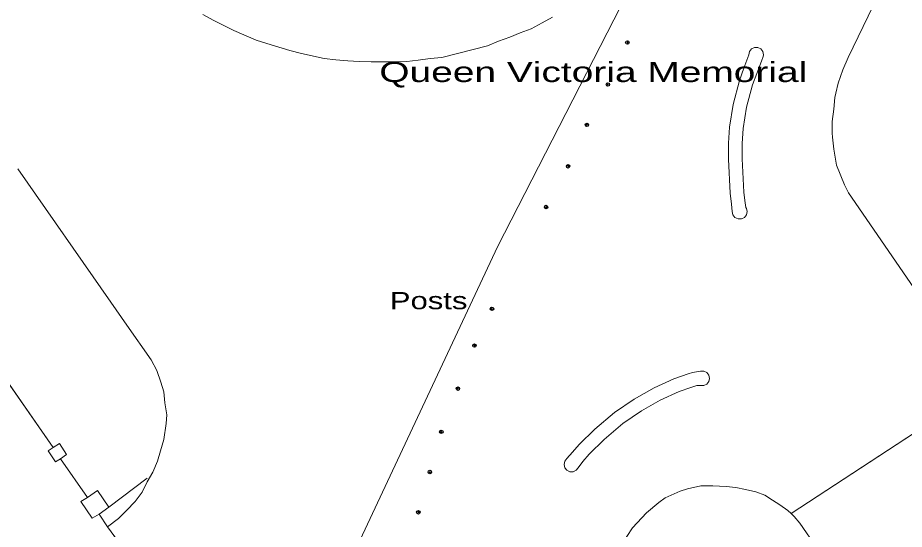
# Model space of a CAD drawing. Extents: x 528790 to 529292, y 179350 to 179856.
# Drawn here: x 529122.8 to 529200.1, y 179668.3 to 179712.9 of the extents above; entities that cross this region are included whole.
import ezdxf

# ---------------------------------------------------------------- set-up
doc = ezdxf.new("R2010")
doc.units = 0
doc.header["$LTSCALE"] = 0.6
doc.header["$PDMODE"] = 32
doc.header["$PDSIZE"] = 0.3
doc.layers.add('1', color=7, linetype='Continuous', lineweight=13)
doc.layers.add('2', color=7, linetype='Continuous', lineweight=13)
doc.layers.add('3', color=7, linetype='Continuous')
doc.layers.add('5', color=7, linetype='Continuous')

msp = doc.modelspace()

# ---------------------------------------------------------------- linework, layer by layer
at = {"layer": '1'}
for points in [[(529204.29, 179733.98), (529185.48, 179736.56), (529185.29, 179734.94), (529184.88, 179732.7), (529184.31, 179730.49), (529183.69, 179728.59), (529182.98, 179726.73), (529182.04, 179724.7), (529180.94, 179722.75), (529179.97, 179721.29), (529178.9, 179719.89), (529177.76, 179718.55), (529164.6, 179692.9), (529149.59, 179660.85)], [(529200.75, 179720.2), (529199.75, 179718.05), (529198.6, 179716), (529197.4, 179713.9), (529195.2, 179709.4), (529194.75, 179708.3), (529194.35, 179707.15), (529194.14, 179706.28), (529194.05, 179705.9), (529193.95, 179704.9), (529193.8, 179703.8), (529193.8, 179702.8), (529193.84, 179702.45), (529193.95, 179701.4), (529194.2, 179700), (529194.9, 179698.3), (529195.25, 179697.6), (529206.95, 179680.56)], [(529149.59, 179660.85), (529164.6, 179692.9), (529177.76, 179718.55)], [(529175.4, 179666.9), (529176.4, 179668.4), (529177.6, 179669.7), (529178.7, 179670.6), (529179.25, 179671), (529180.55, 179671.6), (529181.2, 179671.8), (529182.35, 179672.05), (529183.4, 179672.05), (529184.55, 179672), (529185.4, 179671.9), (529186.25, 179671.75), (529187.15, 179671.55), (529187.95, 179671.25), (529188.6, 179670.8), (529189.25, 179670.4), (529189.95, 179669.9), (529190.23, 179669.65), (529206.95, 179680.56), (529195.25, 179697.6), (529194.9, 179698.3), (529194.2, 179700), (529193.95, 179701.4), (529193.84, 179702.45), (529193.8, 179702.8), (529193.8, 179703.8), (529193.95, 179704.9), (529194.05, 179705.9), (529194.14, 179706.28), (529194.35, 179707.15), (529194.75, 179708.3), (529195.2, 179709.4), (529197.4, 179713.9)], [(529138.9, 179713.15), (529139.8, 179712.65), (529140.92, 179712.09), (529141.6, 179711.75), (529143.55, 179710.9), (529144.5, 179710.6), (529146.5, 179710), (529147.5, 179709.75), (529149.5, 179709.3), (529150.5, 179709.2), (529151.55, 179709.1), (529152.55, 179709.05), (529153.6, 179709), (529155.6, 179709), (529156.7, 179709.05), (529157.7, 179709.15), (529158.75, 179709.3), (529159.75, 179709.4), (529163.75, 179710.4), (529164.7, 179710.8), (529165.7, 179711.15), (529166.6, 179711.55), (529167.55, 179711.9), (529168.5, 179712.4), (529169.4, 179712.9)], [(529169.4, 179712.9), (529168.5, 179712.4), (529167.55, 179711.9), (529166.6, 179711.55), (529165.7, 179711.15), (529164.7, 179710.8), (529163.75, 179710.4), (529159.75, 179709.4), (529158.75, 179709.3), (529157.7, 179709.15), (529156.7, 179709.05), (529155.6, 179709), (529153.6, 179709), (529152.55, 179709.05), (529151.55, 179709.1), (529150.5, 179709.2), (529149.5, 179709.3), (529147.5, 179709.75), (529146.5, 179710), (529144.5, 179710.6), (529143.55, 179710.9), (529141.6, 179711.75), (529140.92, 179712.09), (529139.8, 179712.65), (529138.9, 179713.15)], [(529118, 179686.65), (529125.85, 179675.4), (529126.4, 179675.75), (529127, 179674.8), (529126.5, 179674.4), (529128.85, 179671.05), (529129.7, 179671.65), (529130.7, 179670.2), (529129.85, 179669.6), (529130.6, 179668.5), (529131.55, 179669.2), (529132.25, 179669.9), (529133, 179670.7), (529133.6, 179671.5), (529134.05, 179672.4), (529134.55, 179673.25), (529134.95, 179674.2), (529135.2, 179675.1), (529135.5, 179676.1), (529135.7, 179677.5), (529135.75, 179678.25), (529135.6, 179679.3), (529135.5, 179680.25), (529135.25, 179681.1), (529134.9, 179682.1), (529134.4, 179683.05), (529132.28, 179686.07), (529130.88, 179688.08), (529122.75, 179699.7)], [(529122.75, 179699.7), (529130.88, 179688.08), (529132.28, 179686.07), (529134.4, 179683.05), (529134.9, 179682.1), (529135.25, 179681.1), (529135.5, 179680.25)], [(529132.75, 179665.55), (529130.6, 179668.5), (529129.85, 179669.6), (529129.25, 179669.25), (529128.25, 179670.7), (529128.85, 179671.05), (529126.5, 179674.4), (529126.05, 179674.15), (529125.4, 179675.1), (529125.85, 179675.4), (529118, 179686.65)], [(529231.963, 179644.552), (529215.3, 179668.7), (529214.4, 179668.05), (529213.7, 179669.2), (529214.4, 179669.7), (529210.637, 179675.185), (529206.95, 179680.56), (529190.23, 179669.65), (529190.5, 179669.4), (529191, 179668.8), (529193.969, 179664.512)], [(529135.5, 179680.25), (529135.6, 179679.3), (529135.75, 179678.25), (529135.7, 179677.5), (529135.5, 179676.1), (529135.2, 179675.1), (529134.95, 179674.2), (529134.55, 179673.25), (529134.05, 179672.4), (529133.6, 179671.5), (529133, 179670.7), (529132.25, 179669.9), (529131.55, 179669.2), (529130.6, 179668.5), (529132.75, 179665.55)], [(529193.969, 179664.512), (529191, 179668.8), (529190.5, 179669.4), (529190.23, 179669.65), (529189.95, 179669.9), (529189.25, 179670.4), (529188.6, 179670.8), (529187.95, 179671.25), (529187.15, 179671.55), (529186.25, 179671.75), (529185.4, 179671.9), (529184.55, 179672), (529183.4, 179672.05), (529182.35, 179672.05), (529181.2, 179671.8), (529180.55, 179671.6), (529179.25, 179671), (529178.7, 179670.6), (529177.6, 179669.7), (529176.4, 179668.4), (529175.4, 179666.9)]]:
    msp.add_lwpolyline(points, dxfattribs=at)
for points in [[(529187.244, 179707.999), (529187.74, 179709.31), (529187.77, 179709.35), (529187.83, 179709.63), (529187.77, 179709.91), (529187.59, 179710.14), (529187.32, 179710.27), (529187.03, 179710.27), (529186.77, 179710.14), (529186.59, 179709.91), (529186.53, 179709.63), (529186.106, 179708.453), (529185.72, 179707.38), (529185.17, 179705.3), (529184.85, 179703.32), (529184.76, 179701.93), (529184.77, 179700.54), (529184.91, 179697.56), (529185.03, 179696.61), (529185.09, 179695.96), (529185.15, 179695.68), (529185.33, 179695.45), (529185.6, 179695.32), (529185.89, 179695.32), (529186.15, 179695.45), (529186.33, 179695.68), (529186.39, 179695.96), (529186.33, 179696.24), (529186.28, 179696.31), (529186.202, 179696.926), (529186.11, 179697.66), (529185.97, 179700.57), (529185.96, 179701.9), (529186.04, 179703.19), (529186.34, 179705.05), (529186.87, 179707.01)], [(529185.33, 179695.45), (529185.15, 179695.68), (529185.09, 179695.96), (529185.03, 179696.61), (529184.91, 179697.56), (529184.77, 179700.54), (529184.76, 179701.93), (529184.85, 179703.32), (529185.17, 179705.3), (529185.72, 179707.38), (529186.106, 179708.453), (529186.53, 179709.63), (529186.59, 179709.91), (529186.77, 179710.14), (529187.03, 179710.27), (529187.32, 179710.27), (529187.59, 179710.14), (529187.77, 179709.91), (529187.83, 179709.63), (529187.77, 179709.35), (529187.74, 179709.31), (529187.244, 179707.999), (529186.87, 179707.01), (529186.34, 179705.05), (529186.04, 179703.19), (529185.96, 179701.9), (529185.97, 179700.57), (529186.11, 179697.66), (529186.202, 179696.926), (529186.28, 179696.31), (529186.33, 179696.24), (529186.39, 179695.96), (529186.33, 179695.68), (529186.15, 179695.45), (529185.89, 179695.32), (529185.6, 179695.32)], [(529170.67, 179673.42), (529170.48, 179673.64), (529170.42, 179673.93), (529170.48, 179674.21), (529170.67, 179674.44), (529171.15, 179674.98), (529171.74, 179675.65), (529173.1, 179676.99), (529174.83, 179678.44), (529176.53, 179679.62), (529178.27, 179680.6), (529180.01, 179681.39), (529181.242, 179681.808), (529181.63, 179681.94), (529182.32, 179682.06), (529182.61, 179682.06), (529182.88, 179681.93), (529183.06, 179681.71), (529183.12, 179681.42), (529183.06, 179681.14), (529182.88, 179680.91), (529182.61, 179680.79), (529182.32, 179680.79), (529182.01, 179680.81), (529181.481, 179680.63), (529180.45, 179680.28), (529178.81, 179679.53), (529177.17, 179678.6), (529175.56, 179677.49), (529173.91, 179676.1), (529172.61, 179674.83), (529172.05, 179674.19), (529171.66, 179673.64), (529171.48, 179673.42), (529171.22, 179673.29), (529170.93, 179673.29)], [(529182.88, 179680.91), (529183.06, 179681.14), (529183.12, 179681.42), (529183.06, 179681.71), (529182.88, 179681.93), (529182.61, 179682.06), (529182.32, 179682.06), (529181.63, 179681.94), (529181.242, 179681.808), (529180.01, 179681.39), (529178.27, 179680.6), (529176.53, 179679.62), (529174.83, 179678.44), (529173.1, 179676.99), (529171.74, 179675.65), (529171.15, 179674.98), (529170.67, 179674.44), (529170.48, 179674.21), (529170.42, 179673.93), (529170.48, 179673.64), (529170.67, 179673.42), (529170.93, 179673.29), (529171.22, 179673.29), (529171.48, 179673.42), (529171.66, 179673.64), (529172.05, 179674.19), (529172.61, 179674.83), (529173.91, 179676.1), (529175.56, 179677.49), (529177.17, 179678.6), (529178.81, 179679.53), (529180.45, 179680.28), (529181.481, 179680.63), (529182.01, 179680.81), (529182.32, 179680.79), (529182.61, 179680.79)], [(529126.5, 179674.4), (529127, 179674.8), (529126.4, 179675.75), (529125.85, 179675.4), (529125.4, 179675.1), (529126.05, 179674.15)], [(529129.85, 179669.6), (529130.7, 179670.2), (529129.7, 179671.65), (529128.85, 179671.05), (529128.25, 179670.7), (529129.25, 179669.25)]]:
    msp.add_lwpolyline(points, close=True, dxfattribs=at)
at = {"layer": '2'}
for p, q in [((529118, 179686.65), (529125.85, 179675.4)), ((529190.23, 179669.65), (529206.95, 179680.56)), ((529126.5, 179674.4), (529128.85, 179671.05)), ((529130.7, 179670.2), (529134.043, 179672.72)), ((529129.85, 179669.6), (529130.7, 179670.2)), ((529129.85, 179669.6), (529130.6, 179668.5)), ((529130.6, 179668.5), (529132.75, 179665.55))]:
    msp.add_line(p, q, dxfattribs=at)
for points in [[(529206.95, 179680.56), (529195.25, 179697.6), (529194.9, 179698.3), (529194.2, 179700), (529193.95, 179701.4), (529193.84, 179702.45), (529193.8, 179702.8), (529193.8, 179703.8), (529193.95, 179704.9), (529194.05, 179705.9), (529194.14, 179706.28), (529194.35, 179707.15), (529194.75, 179708.3), (529195.2, 179709.4), (529197.4, 179713.9), (529198.6, 179716), (529199.75, 179718.05), (529200.75, 179720.2)], [(529177.76, 179718.55), (529164.6, 179692.9), (529149.59, 179660.85)], [(529138.9, 179713.15), (529139.8, 179712.65), (529140.92, 179712.09), (529141.6, 179711.75), (529143.55, 179710.9), (529144.5, 179710.6), (529146.5, 179710), (529147.5, 179709.75), (529149.5, 179709.3), (529150.5, 179709.2), (529151.55, 179709.1), (529152.55, 179709.05), (529153.6, 179709), (529155.6, 179709), (529156.7, 179709.05), (529157.7, 179709.15), (529158.75, 179709.3), (529159.75, 179709.4), (529163.75, 179710.4), (529164.7, 179710.8), (529165.7, 179711.15), (529166.6, 179711.55), (529167.55, 179711.9), (529168.5, 179712.4), (529169.4, 179712.9)], [(529130.6, 179668.5), (529131.55, 179669.2), (529132.25, 179669.9), (529133, 179670.7), (529133.6, 179671.5), (529134.05, 179672.4), (529134.55, 179673.25), (529134.95, 179674.2), (529135.2, 179675.1), (529135.5, 179676.1), (529135.7, 179677.5), (529135.75, 179678.25), (529135.6, 179679.3), (529135.5, 179680.25), (529135.25, 179681.1), (529134.9, 179682.1), (529134.4, 179683.05), (529132.28, 179686.07), (529130.88, 179688.08), (529122.75, 179699.7)], [(529126.5, 179674.4), (529127, 179674.8), (529126.4, 179675.75), (529125.85, 179675.4)], [(529126.5, 179674.4), (529126.05, 179674.15), (529125.4, 179675.1), (529125.85, 179675.4)], [(529171.24, 179653.2), (529175, 179666.1), (529175.4, 179666.9), (529176.4, 179668.4), (529177.6, 179669.7), (529178.7, 179670.6), (529179.25, 179671), (529180.55, 179671.6), (529181.2, 179671.8), (529182.35, 179672.05), (529183.4, 179672.05), (529184.55, 179672), (529185.4, 179671.9), (529186.25, 179671.75), (529187.15, 179671.55), (529187.95, 179671.25), (529188.6, 179670.8), (529189.25, 179670.4), (529189.95, 179669.9), (529190.23, 179669.65)], [(529130.7, 179670.2), (529129.7, 179671.65), (529128.85, 179671.05)], [(529129.85, 179669.6), (529129.25, 179669.25), (529128.25, 179670.7), (529128.85, 179671.05)], [(529190.23, 179669.65), (529190.5, 179669.4), (529191, 179668.8), (529193.969, 179664.512), (529198.2, 179658.4)]]:
    msp.add_lwpolyline(points, dxfattribs=at)
for points in [[(529187.244, 179707.999), (529186.87, 179707.01), (529186.34, 179705.05), (529186.04, 179703.19), (529185.96, 179701.9), (529185.97, 179700.57), (529186.11, 179697.66), (529186.202, 179696.926), (529186.28, 179696.31), (529186.33, 179696.24), (529186.39, 179695.96), (529186.33, 179695.68), (529186.15, 179695.45), (529185.89, 179695.32), (529185.6, 179695.32), (529185.33, 179695.45), (529185.15, 179695.68), (529185.09, 179695.96), (529185.03, 179696.61), (529184.91, 179697.56), (529184.77, 179700.54), (529184.76, 179701.93), (529184.85, 179703.32), (529185.17, 179705.3), (529185.72, 179707.38), (529186.106, 179708.453), (529186.53, 179709.63), (529186.59, 179709.91), (529186.77, 179710.14), (529187.03, 179710.27), (529187.32, 179710.27), (529187.59, 179710.14), (529187.77, 179709.91), (529187.83, 179709.63), (529187.77, 179709.35), (529187.74, 179709.31)], [(529181.481, 179680.63), (529182.01, 179680.81), (529182.32, 179680.79), (529182.61, 179680.79), (529182.88, 179680.91), (529183.06, 179681.14), (529183.12, 179681.42), (529183.06, 179681.71), (529182.88, 179681.93), (529182.61, 179682.06), (529182.32, 179682.06), (529181.63, 179681.94), (529181.242, 179681.808), (529180.01, 179681.39), (529178.27, 179680.6), (529176.53, 179679.62), (529174.83, 179678.44), (529173.1, 179676.99), (529171.74, 179675.65), (529171.15, 179674.98), (529170.67, 179674.44), (529170.48, 179674.21), (529170.42, 179673.93), (529170.48, 179673.64), (529170.67, 179673.42), (529170.93, 179673.29), (529171.22, 179673.29), (529171.48, 179673.42), (529171.66, 179673.64), (529172.05, 179674.19), (529172.61, 179674.83), (529173.91, 179676.1), (529175.56, 179677.49), (529177.17, 179678.6), (529178.81, 179679.53), (529180.45, 179680.28)]]:
    msp.add_lwpolyline(points, close=True, dxfattribs=at)
at = {"layer": '3'}
for p in [(529175.944, 179710.692), (529174.248, 179707.033), (529172.413, 179703.512), (529170.772, 179699.908), (529168.855, 179696.359), (529164.13, 179687.49), (529162.6, 179684.28), (529161.16, 179680.53), (529159.71, 179676.77), (529158.71, 179673.26), (529157.71, 179669.75)]:
    msp.add_point(p, dxfattribs=at)

# ---------------------------------------------------------------- texts
at = {"layer": '5'}
for s, height, width, p in [('Queen Victoria Memorial', 1.75, 1.45, (529154.3, 179707.25)), ('Posts', 1.5, 1.35, (529155.22, 179687.45))]:
    msp.add_text(s, height=height, dxfattribs=dict(at, width=width)).set_placement(p)

doc.saveas('drawing.dxf')
